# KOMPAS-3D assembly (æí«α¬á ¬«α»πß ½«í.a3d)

Referenced files in D:\МОДЕЛЬ ТАНКА Т90\ДЕТАЛИ\КОРПУС\МЕТАЛЛ\КОРПУС ЛИТОЙ\: корпус лобовая.m3d
Referenced files in D:\МОДЕЛЬ ТАНКА Т90\ДЕТАЛИ\КОРПУС\МЕТАЛЛ\КОРПУС ШТАМПОВКА\ПЛАСТИК\: пластик лоб.m3d
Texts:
  Сборка корпус лоб  с пластиком
  stalker61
